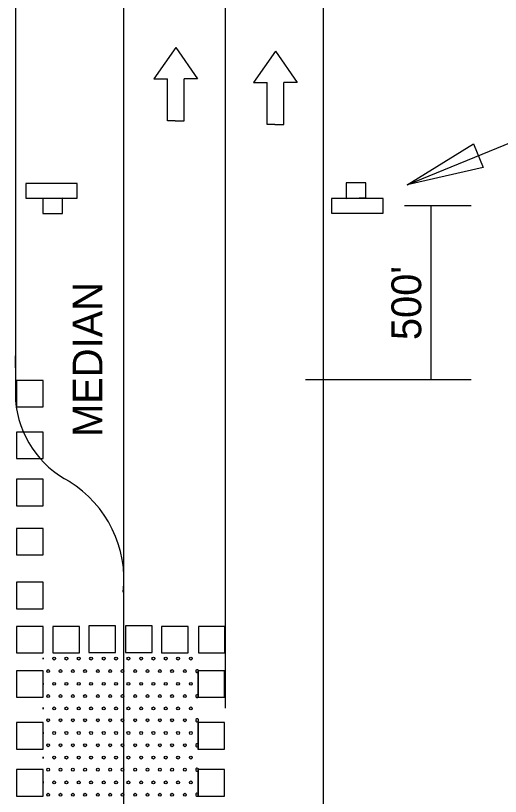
# Model space of a CAD drawing. Extents: x 1531.4 to 1538.6, y 1528.5 to 1539.8.
# Drawn here: x 1534.731 to 1535.707, y 1536.813 to 1538.385 of the extents above; entities that cross this region are included whole.
import ezdxf

# ---------------------------------------------------------------- set-up
doc = ezdxf.new("R2010")
doc.units = 0
for name, color, linetype in [('DETL-DIMS', 7, 'Continuous'), ('DETL-LINE', 7, 'Continuous'), ('DETL-NOTE', 7, 'Continuous'), ('USER-BORD', 7, 'Continuous')]:
    doc.layers.add(name, color=color, linetype=linetype)

# ---------------------------------------------------------------- blocks, each defined once
blk = doc.blocks.new('CD2')
at = {"layer": 'USER-BORD'}
blk.add_lwpolyline([(-0.0062, -0.0062), (0, -0.0062), (0, 0), (-0.0062, 0)], close=True, dxfattribs=at)
blk = doc.blocks.new('DIR')
at = {"layer": 'USER-BORD'}
for p, q in [((0, 0.0001), (-0.0034, -0.0048)), ((0, 0.0001), (0.0034, -0.0048)), ((-0.0034, -0.0048), (-0.0013, -0.0048)), ((-0.0013, -0.0113), (-0.0013, -0.0048)), ((0.0034, -0.0048), (0.0013, -0.0048)), ((0.0013, -0.0113), (0.0013, -0.0048)), ((-0.0001, -0.0113), (-0.0013, -0.0113)), ((-0.0001, -0.0113), (0.0001, -0.0113)), ((0.0001, -0.0113), (0.0013, -0.0113))]:
    blk.add_line(p, q, dxfattribs=at)
blk = doc.blocks.new('SIGN')
at = {"layer": 'USER-BORD'}
for points in [[(-0.0013, 0.0018), (0.0011, 0.0019), (0.0011, 0.0037), (-0.0013, 0.0037)], [(-0.0031, 0.0018), (-0.0031, 0), (0.0032, 0), (0.0032, 0.0018)]]:
    blk.add_lwpolyline(points, close=True, dxfattribs=at)

msp = doc.modelspace()

# ---------------------------------------------------------------- linework, layer by layer
at = {"layer": 'DETL-DIMS'}
for p, q in [((1535.5194, 1538.0446), (1535.7735, 1538.1484)), ((1535.514, 1538.0029), (1535.6482, 1538.0029)), ((1535.5666, 1538.0029), (1535.5666, 1537.6524)), ((1535.3146, 1537.6524), (1535.6482, 1537.6524))]:
    msp.add_line(p, q, dxfattribs=at)
msp.add_lwpolyline([(1535.6527, 1538.1272), (1535.6724, 1538.0794), (1535.5194, 1538.0446)], close=True, dxfattribs=at)
at = {"layer": 'DETL-LINE'}
for p, q in [((1535.153, 1539.6093), (1535.153, 1536.9908)), ((1534.7308, 1539.1023), (1534.7308, 1537.6532)), ((1534.948, 1539.1023), (1534.948, 1536.5764)), ((1535.3502, 1539.1023), (1535.3502, 1536.5764)), ((1534.948, 1537.8145), (1534.948, 1537.0717)), ((1534.7308, 1537.6756), (1534.7308, 1537.6998)), ((1534.7308, 1537.6532), (1534.7308, 1537.6102)), ((1534.8083, 1537.0905), (1534.8083, 1537.0905)), ((1534.8083, 1537.0905), (1534.8083, 1537.0905)), ((1534.8331, 1537.0905), (1534.8331, 1537.0905)), ((1534.8331, 1537.0905), (1534.8331, 1537.0905)), ((1534.8579, 1537.0905), (1534.8579, 1537.0905)), ((1534.8579, 1537.0905), (1534.8579, 1537.0905)), ((1534.8827, 1537.0905), (1534.8827, 1537.0905)), ((1534.8827, 1537.0905), (1534.8827, 1537.0905)), ((1534.9083, 1537.0905), (1534.9083, 1537.0905)), ((1534.9083, 1537.0905), (1534.9083, 1537.0905)), ((1534.9331, 1537.0905), (1534.9331, 1537.0905)), ((1534.9331, 1537.0905), (1534.9331, 1537.0905)), ((1534.948, 1537.1019), (1534.948, 1536.6746)), ((1534.948, 1537.1019), (1534.948, 1537.0717)), ((1534.9579, 1537.0905), (1534.9579, 1537.0905)), ((1534.9579, 1537.0905), (1534.9579, 1537.0905)), ((1534.9835, 1537.0905), (1534.9835, 1537.0905)), ((1534.9835, 1537.0905), (1534.9835, 1537.0905)), ((1535.0083, 1537.0905), (1535.0083, 1537.0905)), ((1535.0083, 1537.0905), (1535.0083, 1537.0905)), ((1535.0331, 1537.0905), (1535.0331, 1537.0905)), ((1535.0331, 1537.0905), (1535.0331, 1537.0905)), ((1535.0579, 1537.0905), (1535.0579, 1537.0905)), ((1535.0579, 1537.0905), (1535.0579, 1537.0905)), ((1535.0835, 1537.0905), (1535.0835, 1537.0905)), ((1535.0835, 1537.0905), (1535.0835, 1537.0905)), ((1534.7955, 1537.0652), (1534.7955, 1537.0652)), ((1534.7963, 1537.0652), (1534.7963, 1537.0652)), ((1534.8203, 1537.0652), (1534.8203, 1537.0652)), ((1534.8211, 1537.0652), (1534.8211, 1537.0652)), ((1534.8459, 1537.0652), (1534.8459, 1537.0652)), ((1534.8459, 1537.0652), (1534.8459, 1537.0652)), ((1534.8707, 1537.0652), (1534.8707, 1537.0652)), ((1534.8707, 1537.0652), (1534.8707, 1537.0652)), ((1534.8955, 1537.0652), (1534.8955, 1537.0652)), ((1534.8963, 1537.0652), (1534.8963, 1537.0652)), ((1534.9203, 1537.0652), (1534.9203, 1537.0652)), ((1534.9211, 1537.0652), (1534.9211, 1537.0652)), ((1534.9459, 1537.0652), (1534.9459, 1537.0652)), ((1534.9459, 1537.0652), (1534.9459, 1537.0652)), ((1534.9707, 1537.0652), (1534.9707, 1537.0652)), ((1534.9715, 1537.0652), (1534.9715, 1537.0652)), ((1534.9955, 1537.0652), (1534.9955, 1537.0652)), ((1534.9963, 1537.0652), (1534.9963, 1537.0652)), ((1535.0203, 1537.0652), (1535.0203, 1537.0652)), ((1535.0211, 1537.0652), (1535.0211, 1537.0652)), ((1535.0459, 1537.0652), (1535.0459, 1537.0652)), ((1535.0459, 1537.0652), (1535.0459, 1537.0652)), ((1535.0707, 1537.0652), (1535.0707, 1537.0652)), ((1535.0715, 1537.0652), (1535.0715, 1537.0652)), ((1535.0955, 1537.0652), (1535.0955, 1537.0652)), ((1535.0963, 1537.0652), (1535.0963, 1537.0652)), ((1534.8083, 1537.0396), (1534.8083, 1537.0396)), ((1534.8331, 1537.0396), (1534.8331, 1537.0396)), ((1534.8579, 1537.0396), (1534.8579, 1537.0396)), ((1534.8827, 1537.0396), (1534.8827, 1537.0396)), ((1534.9083, 1537.0396), (1534.9083, 1537.0396)), ((1534.9331, 1537.0396), (1534.9331, 1537.0396)), ((1534.9579, 1537.0396), (1534.9579, 1537.0396)), ((1534.9835, 1537.0396), (1534.9835, 1537.0396)), ((1535.0083, 1537.0396), (1535.0083, 1537.0396)), ((1535.0331, 1537.0396), (1535.0331, 1537.0396)), ((1535.0579, 1537.0396), (1535.0579, 1537.0396)), ((1535.0835, 1537.0396), (1535.0835, 1537.0396)), ((1534.7955, 1537.0148), (1534.7955, 1537.0148)), ((1534.7963, 1537.0148), (1534.7963, 1537.0148)), ((1534.8203, 1537.0148), (1534.8203, 1537.0148)), ((1534.8211, 1537.0148), (1534.8211, 1537.0148)), ((1534.8459, 1537.0148), (1534.8459, 1537.0148)), ((1534.8459, 1537.0148), (1534.8459, 1537.0148)), ((1534.8707, 1537.0148), (1534.8707, 1537.0148)), ((1534.8707, 1537.0148), (1534.8707, 1537.0148)), ((1534.8955, 1537.0148), (1534.8955, 1537.0148)), ((1534.8963, 1537.0148), (1534.8963, 1537.0148)), ((1534.9203, 1537.0148), (1534.9203, 1537.0148)), ((1534.9211, 1537.0148), (1534.9211, 1537.0148)), ((1534.9459, 1537.0148), (1534.9459, 1537.0148)), ((1534.9459, 1537.0148), (1534.9459, 1537.0148)), ((1534.9707, 1537.0148), (1534.9707, 1537.0148)), ((1534.9715, 1537.0148), (1534.9715, 1537.0148)), ((1534.9955, 1537.0148), (1534.9955, 1537.0148)), ((1534.9963, 1537.0148), (1534.9963, 1537.0148)), ((1535.0203, 1537.0148), (1535.0203, 1537.0148)), ((1535.0211, 1537.0148), (1535.0211, 1537.0148)), ((1535.0459, 1537.0148), (1535.0459, 1537.0148)), ((1535.0459, 1537.0148), (1535.0459, 1537.0148)), ((1535.0707, 1537.0148), (1535.0707, 1537.0148)), ((1535.0715, 1537.0148), (1535.0715, 1537.0148)), ((1535.0955, 1537.0148), (1535.0955, 1537.0148)), ((1535.0963, 1537.0148), (1535.0963, 1537.0148)), ((1534.8083, 1536.99), (1534.8083, 1536.99)), ((1534.8083, 1536.99), (1534.8083, 1536.99)), ((1534.8331, 1536.99), (1534.8331, 1536.99)), ((1534.8331, 1536.99), (1534.8331, 1536.99)), ((1534.8579, 1536.99), (1534.8579, 1536.99)), ((1534.8579, 1536.99), (1534.8579, 1536.99)), ((1534.8827, 1536.99), (1534.8827, 1536.99)), ((1534.8827, 1536.99), (1534.8827, 1536.99)), ((1534.9083, 1536.99), (1534.9083, 1536.99)), ((1534.9083, 1536.99), (1534.9083, 1536.99)), ((1534.9331, 1536.99), (1534.9331, 1536.99)), ((1534.9331, 1536.99), (1534.9331, 1536.99)), ((1534.9579, 1536.99), (1534.9579, 1536.99)), ((1534.9579, 1536.99), (1534.9579, 1536.99)), ((1534.9835, 1536.99), (1534.9835, 1536.99)), ((1534.9835, 1536.99), (1534.9835, 1536.99)), ((1535.0083, 1536.99), (1535.0083, 1536.99)), ((1535.0083, 1536.99), (1535.0083, 1536.99)), ((1535.0331, 1536.99), (1535.0331, 1536.99)), ((1535.0331, 1536.99), (1535.0331, 1536.99)), ((1535.0579, 1536.99), (1535.0579, 1536.99)), ((1535.0579, 1536.99), (1535.0579, 1536.99)), ((1535.0835, 1536.99), (1535.0835, 1536.99)), ((1535.0835, 1536.99), (1535.0835, 1536.99)), ((1534.7955, 1536.9662), (1534.7955, 1536.9662)), ((1534.7963, 1536.9662), (1534.7963, 1536.9662)), ((1534.8203, 1536.9662), (1534.8203, 1536.9662)), ((1534.8211, 1536.9662), (1534.8211, 1536.9662)), ((1534.8459, 1536.9662), (1534.8459, 1536.9662)), ((1534.8459, 1536.9662), (1534.8459, 1536.9662)), ((1534.8707, 1536.9662), (1534.8707, 1536.9662)), ((1534.8707, 1536.9662), (1534.8707, 1536.9662)), ((1534.8955, 1536.9662), (1534.8955, 1536.9662)), ((1534.8963, 1536.9662), (1534.8963, 1536.9662)), ((1534.9203, 1536.9662), (1534.9203, 1536.9662)), ((1534.9211, 1536.9662), (1534.9211, 1536.9662)), ((1534.9459, 1536.9662), (1534.9459, 1536.9662)), ((1534.9459, 1536.9662), (1534.9459, 1536.9662)), ((1534.9707, 1536.9662), (1534.9707, 1536.9662)), ((1534.9715, 1536.9662), (1534.9715, 1536.9662)), ((1534.9955, 1536.9662), (1534.9955, 1536.9662)), ((1534.9963, 1536.9662), (1534.9963, 1536.9662)), ((1535.0203, 1536.9662), (1535.0203, 1536.9662)), ((1535.0211, 1536.9662), (1535.0211, 1536.9662)), ((1535.0459, 1536.9662), (1535.0459, 1536.9662)), ((1535.0459, 1536.9662), (1535.0459, 1536.9662)), ((1535.0707, 1536.9662), (1535.0707, 1536.9662)), ((1535.0715, 1536.9662), (1535.0715, 1536.9662)), ((1535.0955, 1536.9662), (1535.0955, 1536.9662)), ((1535.0963, 1536.9662), (1535.0963, 1536.9662)), ((1534.8083, 1536.9406), (1534.8083, 1536.9406)), ((1534.8331, 1536.9406), (1534.8331, 1536.9406)), ((1534.8579, 1536.9406), (1534.8579, 1536.9406)), ((1534.8827, 1536.9406), (1534.8827, 1536.9406)), ((1534.9083, 1536.9406), (1534.9083, 1536.9406)), ((1534.9331, 1536.9406), (1534.9331, 1536.9406)), ((1534.9579, 1536.9406), (1534.9579, 1536.9406)), ((1534.9835, 1536.9406), (1534.9835, 1536.9406)), ((1535.0083, 1536.9406), (1535.0083, 1536.9406)), ((1535.0331, 1536.9406), (1535.0331, 1536.9406)), ((1535.0579, 1536.9406), (1535.0579, 1536.9406)), ((1535.0835, 1536.9406), (1535.0835, 1536.9406)), ((1534.7955, 1536.9158), (1534.7955, 1536.9158)), ((1534.7963, 1536.9158), (1534.7963, 1536.9158)), ((1534.8203, 1536.9158), (1534.8203, 1536.9158)), ((1534.8211, 1536.9158), (1534.8211, 1536.9158)), ((1534.8459, 1536.9158), (1534.8459, 1536.9158)), ((1534.8459, 1536.9158), (1534.8459, 1536.9158)), ((1534.8707, 1536.9158), (1534.8707, 1536.9158)), ((1534.8707, 1536.9158), (1534.8707, 1536.9158)), ((1534.8955, 1536.9158), (1534.8955, 1536.9158)), ((1534.8963, 1536.9158), (1534.8963, 1536.9158)), ((1534.9203, 1536.9158), (1534.9203, 1536.9158)), ((1534.9211, 1536.9158), (1534.9211, 1536.9158)), ((1534.9459, 1536.9158), (1534.9459, 1536.9158)), ((1534.9459, 1536.9158), (1534.9459, 1536.9158)), ((1534.9707, 1536.9158), (1534.9707, 1536.9158)), ((1534.9715, 1536.9158), (1534.9715, 1536.9158)), ((1534.9955, 1536.9158), (1534.9955, 1536.9158)), ((1534.9963, 1536.9158), (1534.9963, 1536.9158)), ((1535.0203, 1536.9158), (1535.0203, 1536.9158)), ((1535.0211, 1536.9158), (1535.0211, 1536.9158)), ((1535.0459, 1536.9158), (1535.0459, 1536.9158)), ((1535.0459, 1536.9158), (1535.0459, 1536.9158)), ((1535.0707, 1536.9158), (1535.0707, 1536.9158)), ((1535.0715, 1536.9158), (1535.0715, 1536.9158)), ((1535.0955, 1536.9158), (1535.0955, 1536.9158)), ((1535.0963, 1536.9158), (1535.0963, 1536.9158)), ((1534.8083, 1536.891), (1534.8083, 1536.891)), ((1534.8083, 1536.891), (1534.8083, 1536.891)), ((1534.8331, 1536.891), (1534.8331, 1536.891)), ((1534.8331, 1536.891), (1534.8331, 1536.891)), ((1534.8579, 1536.891), (1534.8579, 1536.891)), ((1534.8579, 1536.891), (1534.8579, 1536.891)), ((1534.8827, 1536.891), (1534.8827, 1536.891)), ((1534.8827, 1536.891), (1534.8827, 1536.891)), ((1534.9083, 1536.891), (1534.9083, 1536.891)), ((1534.9083, 1536.891), (1534.9083, 1536.891)), ((1534.9331, 1536.891), (1534.9331, 1536.891)), ((1534.9331, 1536.891), (1534.9331, 1536.891)), ((1534.9579, 1536.891), (1534.9579, 1536.891)), ((1534.9579, 1536.891), (1534.9579, 1536.891)), ((1534.9835, 1536.891), (1534.9835, 1536.891)), ((1534.9835, 1536.891), (1534.9835, 1536.891)), ((1535.0083, 1536.891), (1535.0083, 1536.891)), ((1535.0083, 1536.891), (1535.0083, 1536.891)), ((1535.0331, 1536.891), (1535.0331, 1536.891)), ((1535.0331, 1536.891), (1535.0331, 1536.891)), ((1535.0579, 1536.891), (1535.0579, 1536.891)), ((1535.0579, 1536.891), (1535.0579, 1536.891)), ((1535.0835, 1536.891), (1535.0835, 1536.891)), ((1535.0835, 1536.891), (1535.0835, 1536.891)), ((1534.7955, 1536.8666), (1534.7955, 1536.8666)), ((1534.7963, 1536.8666), (1534.7963, 1536.8666)), ((1534.8203, 1536.8666), (1534.8203, 1536.8666)), ((1534.8211, 1536.8666), (1534.8211, 1536.8666)), ((1534.8459, 1536.8666), (1534.8459, 1536.8666)), ((1534.8459, 1536.8666), (1534.8459, 1536.8666)), ((1534.8707, 1536.8666), (1534.8707, 1536.8666)), ((1534.8707, 1536.8666), (1534.8707, 1536.8666)), ((1534.8955, 1536.8666), (1534.8955, 1536.8666)), ((1534.8963, 1536.8666), (1534.8963, 1536.8666)), ((1534.9203, 1536.8666), (1534.9203, 1536.8666)), ((1534.9211, 1536.8666), (1534.9211, 1536.8666)), ((1534.9459, 1536.8666), (1534.9459, 1536.8666)), ((1534.9459, 1536.8666), (1534.9459, 1536.8666)), ((1534.9707, 1536.8666), (1534.9707, 1536.8666)), ((1534.9715, 1536.8666), (1534.9715, 1536.8666)), ((1534.9955, 1536.8666), (1534.9955, 1536.8666)), ((1534.9963, 1536.8666), (1534.9963, 1536.8666)), ((1535.0203, 1536.8666), (1535.0203, 1536.8666)), ((1535.0211, 1536.8666), (1535.0211, 1536.8666)), ((1535.0459, 1536.8666), (1535.0459, 1536.8666)), ((1535.0459, 1536.8666), (1535.0459, 1536.8666)), ((1535.0707, 1536.8666), (1535.0707, 1536.8666)), ((1535.0715, 1536.8666), (1535.0715, 1536.8666)), ((1535.0955, 1536.8666), (1535.0955, 1536.8666)), ((1535.0963, 1536.8666), (1535.0963, 1536.8666)), ((1534.8083, 1536.841), (1534.8083, 1536.841)), ((1534.8331, 1536.841), (1534.8331, 1536.841)), ((1534.8579, 1536.841), (1534.8579, 1536.841)), ((1534.8827, 1536.841), (1534.8827, 1536.841)), ((1534.9083, 1536.841), (1534.9083, 1536.841)), ((1534.9331, 1536.841), (1534.9331, 1536.841)), ((1534.9579, 1536.841), (1534.9579, 1536.841)), ((1534.9835, 1536.841), (1534.9835, 1536.841)), ((1535.0083, 1536.841), (1535.0083, 1536.841)), ((1535.0331, 1536.841), (1535.0331, 1536.841)), ((1535.0579, 1536.841), (1535.0579, 1536.841)), ((1535.0835, 1536.841), (1535.0835, 1536.841)), ((1534.7955, 1536.8162), (1534.7955, 1536.8162)), ((1534.7963, 1536.8162), (1534.7963, 1536.8162)), ((1534.8203, 1536.8162), (1534.8203, 1536.8162)), ((1534.8211, 1536.8162), (1534.8211, 1536.8162)), ((1534.8459, 1536.8162), (1534.8459, 1536.8162)), ((1534.8459, 1536.8162), (1534.8459, 1536.8162)), ((1534.8707, 1536.8162), (1534.8707, 1536.8162)), ((1534.8707, 1536.8162), (1534.8707, 1536.8162)), ((1534.8955, 1536.8162), (1534.8955, 1536.8162)), ((1534.8963, 1536.8162), (1534.8963, 1536.8162)), ((1534.9203, 1536.8162), (1534.9203, 1536.8162)), ((1534.9211, 1536.8162), (1534.9211, 1536.8162)), ((1534.9459, 1536.8162), (1534.9459, 1536.8162)), ((1534.9459, 1536.8162), (1534.9459, 1536.8162)), ((1534.9707, 1536.8162), (1534.9707, 1536.8162)), ((1534.9715, 1536.8162), (1534.9715, 1536.8162)), ((1534.9955, 1536.8162), (1534.9955, 1536.8162)), ((1534.9963, 1536.8162), (1534.9963, 1536.8162)), ((1535.0203, 1536.8162), (1535.0203, 1536.8162)), ((1535.0211, 1536.8162), (1535.0211, 1536.8162)), ((1535.0459, 1536.8162), (1535.0459, 1536.8162)), ((1535.0459, 1536.8162), (1535.0459, 1536.8162)), ((1535.0707, 1536.8162), (1535.0707, 1536.8162)), ((1535.0715, 1536.8162), (1535.0715, 1536.8162)), ((1535.0955, 1536.8162), (1535.0955, 1536.8162)), ((1535.0963, 1536.8162), (1535.0963, 1536.8162))]:
    msp.add_line(p, q, dxfattribs=at)
for points in [[(1535.153, 1537.828), (1535.153, 1537.7093)], [(1535.153, 1537.7093), (1535.153, 1537.5905)], [(1534.786, 1537.0919), (1534.786, 1537.0889)], [(1535.0988, 1537.0658), (1535.0979, 1537.0658), (1535.0979, 1537.0124), (1535.0988, 1537.0124)], [(1535.0988, 1537.0637), (1535.0988, 1537.0667)], [(1535.0988, 1537.0124), (1535.0988, 1537.0658)], [(1534.786, 1537.0411), (1534.786, 1537.0381)], [(1535.0988, 1537.0133), (1535.0988, 1537.0163)], [(1534.786, 1536.9915), (1534.786, 1536.9885)], [(1535.0988, 1536.9646), (1535.0988, 1536.9676)], [(1535.0988, 1536.9615), (1535.0979, 1536.9615), (1535.0979, 1536.9081), (1535.0988, 1536.9081)], [(1535.0988, 1536.9081), (1535.0988, 1536.9615)], [(1534.786, 1536.942), (1534.786, 1536.939)], [(1535.0988, 1536.9142), (1535.0988, 1536.9172)], [(1534.786, 1536.8924), (1534.786, 1536.8894)], [(1535.0988, 1536.8667), (1535.0979, 1536.8667), (1535.0979, 1536.8133), (1535.0988, 1536.8133)], [(1535.0988, 1536.865), (1535.0988, 1536.8681)], [(1535.0988, 1536.8133), (1535.0988, 1536.8667)], [(1534.786, 1536.8425), (1534.786, 1536.8394)], [(1535.0988, 1536.8146), (1535.0988, 1536.8177)]]:
    msp.add_lwpolyline(points, dxfattribs=at)
for centre in [(1534.8083, 1537.0904), (1534.8331, 1537.0904), (1534.8579, 1537.0904), (1534.8827, 1537.0904), (1534.9083, 1537.0904), (1534.9331, 1537.0904), (1534.9579, 1537.0904), (1534.9835, 1537.0904), (1535.0083, 1537.0904), (1535.0331, 1537.0904), (1535.0579, 1537.0904), (1535.0835, 1537.0904), (1534.7963, 1537.0652), (1534.8211, 1537.0652), (1534.8459, 1537.0652), (1534.8707, 1537.0652), (1534.8963, 1537.0652), (1534.9211, 1537.0652), (1534.9459, 1537.0652), (1534.9715, 1537.0652), (1534.9963, 1537.0652), (1535.0211, 1537.0652), (1535.0459, 1537.0652), (1535.0715, 1537.0652), (1534.8083, 1537.0396), (1534.8331, 1537.0396), (1534.8579, 1537.0396), (1534.8827, 1537.0396), (1534.9083, 1537.0396), (1534.9331, 1537.0396), (1534.9579, 1537.0396), (1534.9835, 1537.0396), (1535.0083, 1537.0396), (1535.0331, 1537.0396), (1535.0579, 1537.0396), (1535.0835, 1537.0396), (1534.7963, 1537.0148), (1534.8211, 1537.0148), (1534.8459, 1537.0148), (1534.8707, 1537.0148), (1534.8963, 1537.0148), (1534.9211, 1537.0148), (1534.9459, 1537.0148), (1534.9715, 1537.0148), (1534.9963, 1537.0148), (1535.0211, 1537.0148), (1535.0459, 1537.0148), (1535.0715, 1537.0148), (1534.8083, 1536.99), (1534.8331, 1536.99), (1534.8579, 1536.99), (1534.8827, 1536.99), (1534.9083, 1536.99), (1534.9331, 1536.99), (1534.9579, 1536.99), (1534.9835, 1536.99), (1535.0083, 1536.99), (1535.0331, 1536.99), (1535.0579, 1536.99), (1535.0835, 1536.99), (1534.7963, 1536.9661), (1534.8211, 1536.9661), (1534.8459, 1536.9661), (1534.8707, 1536.9661), (1534.8963, 1536.9661), (1534.9211, 1536.9661), (1534.9459, 1536.9661), (1534.9715, 1536.9661), (1534.9963, 1536.9661), (1535.0211, 1536.9661), (1535.0459, 1536.9661), (1535.0715, 1536.9661), (1534.8083, 1536.9405), (1534.8331, 1536.9405), (1534.8579, 1536.9405), (1534.8827, 1536.9405), (1534.9083, 1536.9405), (1534.9331, 1536.9405), (1534.9579, 1536.9405), (1534.9835, 1536.9405), (1535.0083, 1536.9405), (1535.0331, 1536.9405), (1535.0579, 1536.9405), (1535.0835, 1536.9405), (1534.7963, 1536.9157), (1534.8211, 1536.9157), (1534.8459, 1536.9157), (1534.8707, 1536.9157), (1534.8963, 1536.9157), (1534.9211, 1536.9157), (1534.9459, 1536.9157), (1534.9715, 1536.9157), (1534.9963, 1536.9157), (1535.0211, 1536.9157), (1535.0459, 1536.9157), (1535.0715, 1536.9157), (1534.8083, 1536.8909), (1534.8331, 1536.8909), (1534.8579, 1536.8909), (1534.8827, 1536.8909), (1534.9083, 1536.8909), (1534.9331, 1536.8909), (1534.9579, 1536.8909), (1534.9835, 1536.8909), (1535.0083, 1536.8909), (1535.0331, 1536.8909), (1535.0579, 1536.8909), (1535.0835, 1536.8909), (1534.7963, 1536.8666), (1534.8211, 1536.8666), (1534.8459, 1536.8666), (1534.8707, 1536.8666), (1534.8963, 1536.8666), (1534.9211, 1536.8666), (1534.9459, 1536.8666), (1534.9715, 1536.8666), (1534.9963, 1536.8666), (1535.0211, 1536.8666), (1535.0459, 1536.8666), (1535.0715, 1536.8666), (1534.8083, 1536.841), (1534.8331, 1536.841), (1534.8579, 1536.841), (1534.8827, 1536.841), (1534.9083, 1536.841), (1534.9331, 1536.841), (1534.9579, 1536.841), (1534.9835, 1536.841), (1535.0083, 1536.841), (1535.0331, 1536.841), (1535.0579, 1536.841), (1535.0835, 1536.841), (1534.7963, 1536.8162), (1534.8211, 1536.8162), (1534.8459, 1536.8162), (1534.8707, 1536.8162), (1534.8963, 1536.8162), (1534.9211, 1536.8162), (1534.9459, 1536.8162), (1534.9715, 1536.8162), (1534.9963, 1536.8162), (1535.0211, 1536.8162), (1535.0459, 1536.8162), (1535.0715, 1536.8162)]:
    msp.add_circle(centre, 0.00291, dxfattribs=at)
for centre, radius, start, end in [((1534.9308, 1537.6727), 0.2007, 172.26833333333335, 172.26833611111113), ((1534.9308, 1537.6259), 0.2007, 184.57, 243.0108), ((1534.7159, 1537.2488), 0.2331, 353.8807, 58.2504), ((1534.7835, 1537.0904), 0.00291, 328.8409, 31.1591), ((1535.0963, 1537.0652), 0.00291, 31.1591, 328.8409), ((1534.7835, 1537.0396), 0.00291, 328.8409, 31.1591), ((1535.0963, 1537.0148), 0.00291, 31.1591, 328.8409), ((1534.7835, 1536.99), 0.00291, 328.8409, 31.1591), ((1535.0963, 1536.9661), 0.00291, 31.1591, 328.8409), ((1534.7835, 1536.9405), 0.00291, 328.8409, 31.1591), ((1535.0963, 1536.9157), 0.00291, 31.1591, 328.8409), ((1534.7835, 1536.8909), 0.00291, 328.8409, 31.1591), ((1535.0963, 1536.8666), 0.00291, 31.1591, 328.8409), ((1534.7835, 1536.841), 0.00291, 328.8409, 31.1591), ((1535.0963, 1536.8162), 0.00291, 31.1591, 328.8409)]:
    msp.add_arc(centre, radius, start, end, dxfattribs=at)

# ---------------------------------------------------------------- block references
for name, p, xscale, yscale in [('DIR', (1535.0531, 1538.3197), 12.922428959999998, 12.922428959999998), ('DIR', (1535.2538, 1538.3123), 12.922428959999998, 12.922428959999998), ('SIGN', (1535.4181, 1537.9874), 16.482020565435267, 16.482020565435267), ('CD2', (1534.786, 1537.6507), 8.61495264, 8.61495264), ('CD2', (1534.786, 1537.5466), 8.61495264, 8.61495264), ('CD2', (1534.786, 1537.4516), 8.61495264, 8.61495264), ('CD2', (1534.786, 1537.3526), 8.61495264, 8.61495264), ('CD2', (1534.786, 1537.244), 8.61495264, 8.61495264), ('CD2', (1534.786, 1537.1553), 8.61495264, 8.61495264), ('CD2', (1534.8593, 1537.1553), 8.61495264, 8.61495264), ('CD2', (1534.9316, 1537.1562), 8.61495264, 8.61495264), ('CD2', (1535.0057, 1537.1562), 8.61495264, 8.61495264), ('CD2', (1535.0781, 1537.1553), 8.61495264, 8.61495264), ('CD2', (1535.1522, 1537.1553), 8.61495264, 8.61495264), ('CD2', (1534.786, 1537.0658), 8.61495264, 8.61495264), ('CD2', (1535.1513, 1537.0658), 8.61495264, 8.61495264), ('CD2', (1534.786, 1536.9615), 8.61495264, 8.61495264), ('CD2', (1535.1513, 1536.9615), 8.61495264, 8.61495264), ('CD2', (1534.786, 1536.8667), 8.61495264, 8.61495264), ('CD2', (1535.1513, 1536.8667), 8.61495264, 8.61495264)]:
    msp.add_blockref(name, p, dxfattribs=dict(at, xscale=xscale, yscale=yscale))
at = {"layer": 'DETL-LINE', "xscale": 16.482020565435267, "yscale": 16.482020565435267, "rotation": 180}
msp.add_blockref('SIGN', (1534.8039, 1538.0474), dxfattribs=at)

# ---------------------------------------------------------------- texts
at = {"layer": 'DETL-NOTE'}
for s, p in [("500'", (1535.5475, 1537.7317)), ('MEDIAN', (1534.9056, 1537.5367))]:
    msp.add_text(s, height=0.06, rotation=90, dxfattribs=at).set_placement(p)

doc.saveas('drawing.dxf')
